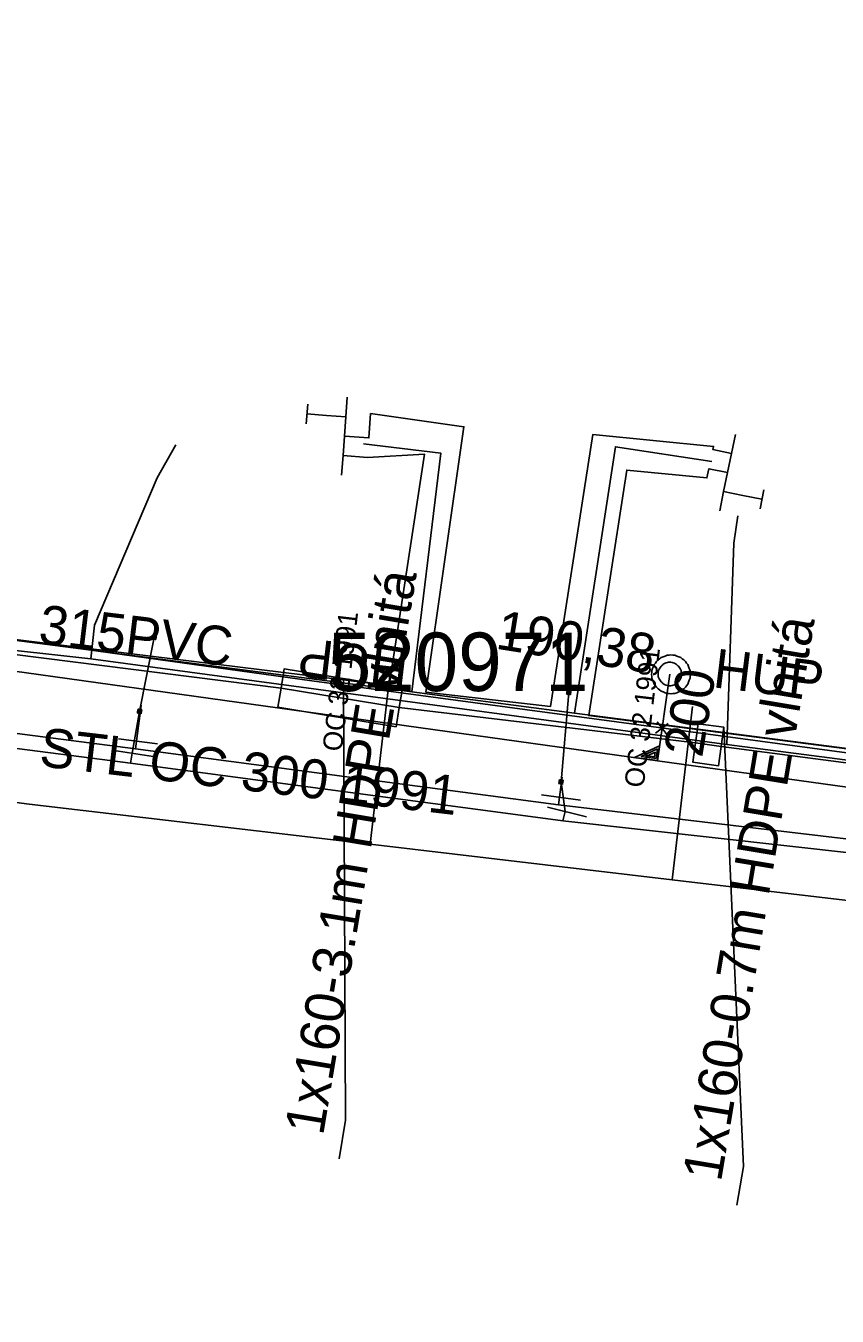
# Model space of a CAD drawing. Extents: x -746464 to -745690, y -1051581 to -1049993.
# Drawn here: x -745918.54 to -745897.73, y -1050642.11 to -1050609 of the extents above; entities that cross this region are included whole.
import ezdxf

# ---------------------------------------------------------------- set-up
doc = ezdxf.new("R2010")
doc.units = 0
for name, color, linetype in [('04_CETIN_sdelovaci_podzem', 7, 'Continuous'), ('45_Eltodo_popisy', 7, 'Continuous'), ('45_Eltodo_vedeni_NN_zemni', 7, 'Continuous'), ('48_Prazs_plynarenska_STL', 7, 'Continuous'), ('48_Prazs_plynarenska_STL_popisy', 7, 'Continuous'), ('51_PVaK_kanal_jednotna_neoverena poloha_pripojka', 7, 'Continuous'), ('51_PVaK_kanal_jednotna_overena poloha_rad', 7, 'Continuous'), ('51_PVaK_kanal_objekty', 7, 'Continuous'), ('51_PVaK_kanal_popisy', 7, 'Continuous'), ('51_PVaK_vodovod_chranicky_objekty', 7, 'Continuous'), ('51_PVaK_vodovod_neoverena poloha_pripojka', 7, 'Continuous'), ('51_PVaK_vodovod_overena poloha_pripojka', 7, 'Continuous'), ('51_PVaK_vodovod_overena poloha_rad', 7, 'Continuous'), ('51_PVaK_vodovod_zruseno_neoverena poloha', 7, 'Continuous'), ('55_PREdi_chranicky', 7, 'Continuous'), ('55_PREdi_NN', 7, 'Continuous'), ('55_PREdi_NN_pripojovaci_misto', 7, 'Continuous'), ('55_PREdi_stavby_popisy', 7, 'Continuous'), ('55_PREdi_VN', 7, 'Continuous')]:
    doc.layers.add(name, color=color, linetype=linetype)

msp = doc.modelspace()

# ---------------------------------------------------------------- linework, layer by layer
at = {"layer": '04_CETIN_sdelovaci_podzem'}
for points in [[(-745863.25, -1050609), (-745863.73, -1050611.95), (-745870.36, -1050631.21), (-745887.77, -1050629.2), (-745891.41, -1050628.63), (-745900.56, -1050627.44)], [(-745916.87, -1050625.24), (-745916.78, -1050624.38), (-745915.17, -1050620.6), (-745914.69, -1050619.75)], [(-745900.27, -1050621.57), (-745900.38, -1050622.27), (-745900.56, -1050627.44)], [(-745916.87, -1050625.24), (-745922.59, -1050624.61), (-745926.58, -1050624.12), (-745928.53, -1050623.83), (-745932.3, -1050623.37), (-745939.73, -1050622.43)], [(-745900.56, -1050627.44), (-745916.87, -1050625.24)]]:
    msp.add_lwpolyline(points, dxfattribs=at)
at = {"layer": '45_Eltodo_vedeni_NN_zemni'}
for points in [[(-745932.464, -1050622.851), (-745911.205, -1050625.806)], [(-745911.205, -1050625.806), (-745891.44, -1050628.465)]]:
    msp.add_lwpolyline(points, dxfattribs=at)
at = {"layer": '48_Prazs_plynarenska_STL'}
for points in [[(-745983.23, -1050618.3), (-745982.423, -1050618.479), (-745972.466, -1050620.693), (-745959.98, -1050623.47), (-745928.028, -1050627.702), (-745918.45, -1050628.97), (-745909.707, -1050630), (-745901.96, -1050630.912), (-745885.25, -1050632.88), (-745867.974, -1050634.924), (-745862.77, -1050635.54), (-745858.93, -1050638.49), (-745858.68, -1050642.05), (-745857.88, -1050642.106)], [(-745909.707, -1050630), (-745909.18, -1050625.527)], [(-745901.96, -1050630.912), (-745901.437, -1050626.468)]]:
    msp.add_lwpolyline(points, dxfattribs=at)
at = {"layer": '51_PVaK_kanal_jednotna_neoverena poloha_pripojka'}
msp.add_line((-745902.02, -1050625.63), (-745902.338, -1050627.854), dxfattribs=at)
at = {"layer": '51_PVaK_kanal_jednotna_overena poloha_rad'}
msp.add_lwpolyline([(-745889.28, -1050629.67), (-745902.338, -1050627.854), (-745923.93, -1050624.851), (-745928.486, -1050624.217), (-745945.72, -1050621.82)], dxfattribs=at)
at = {"layer": '51_PVaK_kanal_objekty'}
for p, q in [((-745902.34, -1050626.853), (-745902.086, -1050627.189)), ((-745902.39, -1050627.15), (-745902.058, -1050626.898))]:
    msp.add_line(p, q, dxfattribs=at)
for points in [[(-745901.49, -1050625.64), (-745901.5, -1050625.59), (-745901.5, -1050625.54), (-745901.52, -1050625.49), (-745901.54, -1050625.44), (-745901.56, -1050625.39), (-745901.59, -1050625.35), (-745901.62, -1050625.31), (-745901.66, -1050625.27), (-745901.7, -1050625.24), (-745901.74, -1050625.21), (-745901.79, -1050625.19), (-745901.84, -1050625.17), (-745901.89, -1050625.15), (-745901.94, -1050625.15), (-745901.99, -1050625.14), (-745902.04, -1050625.15), (-745902.09, -1050625.15), (-745902.14, -1050625.17), (-745902.19, -1050625.19), (-745902.24, -1050625.21), (-745902.28, -1050625.24), (-745902.32, -1050625.27), (-745902.36, -1050625.31), (-745902.39, -1050625.35), (-745902.42, -1050625.39), (-745902.44, -1050625.44), (-745902.46, -1050625.49), (-745902.48, -1050625.54), (-745902.48, -1050625.59), (-745902.49, -1050625.64), (-745902.48, -1050625.69), (-745902.48, -1050625.74), (-745902.46, -1050625.79), (-745902.44, -1050625.84), (-745902.42, -1050625.89), (-745902.39, -1050625.93), (-745902.36, -1050625.97), (-745902.32, -1050626.01), (-745902.28, -1050626.04), (-745902.24, -1050626.07), (-745902.19, -1050626.09), (-745902.14, -1050626.11), (-745902.09, -1050626.13), (-745902.04, -1050626.13), (-745901.99, -1050626.14), (-745901.94, -1050626.13), (-745901.89, -1050626.13), (-745901.84, -1050626.11), (-745901.79, -1050626.09), (-745901.74, -1050626.07), (-745901.7, -1050626.04), (-745901.66, -1050626.01), (-745901.62, -1050625.97), (-745901.59, -1050625.93), (-745901.56, -1050625.89), (-745901.54, -1050625.84), (-745901.52, -1050625.79), (-745901.5, -1050625.74), (-745901.5, -1050625.69), (-745901.49, -1050625.64)], [(-745901.72, -1050625.63), (-745901.72, -1050625.6), (-745901.726, -1050625.57), (-745901.732, -1050625.54), (-745901.744, -1050625.51), (-745901.762, -1050625.48), (-745901.78, -1050625.456), (-745901.798, -1050625.432), (-745901.822, -1050625.408), (-745901.846, -1050625.39), (-745901.87, -1050625.372), (-745901.9, -1050625.354), (-745901.93, -1050625.342), (-745901.96, -1050625.336), (-745901.99, -1050625.33), (-745902.02, -1050625.33), (-745902.05, -1050625.33), (-745902.08, -1050625.336), (-745902.11, -1050625.342), (-745902.14, -1050625.354), (-745902.17, -1050625.372), (-745902.194, -1050625.39), (-745902.218, -1050625.408), (-745902.242, -1050625.432), (-745902.26, -1050625.456), (-745902.278, -1050625.48), (-745902.296, -1050625.51), (-745902.308, -1050625.54), (-745902.314, -1050625.57), (-745902.32, -1050625.6), (-745902.32, -1050625.63), (-745902.32, -1050625.66), (-745902.314, -1050625.69), (-745902.308, -1050625.72), (-745902.296, -1050625.75), (-745902.278, -1050625.78), (-745902.26, -1050625.804), (-745902.242, -1050625.828), (-745902.218, -1050625.852), (-745902.194, -1050625.87), (-745902.17, -1050625.888), (-745902.14, -1050625.906), (-745902.11, -1050625.918), (-745902.08, -1050625.924), (-745902.05, -1050625.93), (-745902.02, -1050625.93), (-745901.99, -1050625.93), (-745901.96, -1050625.924), (-745901.93, -1050625.918), (-745901.9, -1050625.906), (-745901.87, -1050625.888), (-745901.846, -1050625.87), (-745901.822, -1050625.852), (-745901.798, -1050625.828), (-745901.78, -1050625.804), (-745901.762, -1050625.78), (-745901.744, -1050625.75), (-745901.732, -1050625.72), (-745901.726, -1050625.69), (-745901.72, -1050625.66), (-745901.72, -1050625.63)], [(-745902.217, -1050627.018), (-745902.333, -1050627.853), (-745902.929, -1050627.77), (-745902.281, -1050627.476)], [(-745902.336, -1050627.554), (-745902.37, -1050627.797), (-745902.75, -1050627.744), (-745902.332, -1050627.554)], [(-745902.392, -1050627.635), (-745902.409, -1050627.757), (-745902.604, -1050627.73), (-745902.388, -1050627.636)]]:
    msp.add_lwpolyline(points, dxfattribs=at)
at = {"layer": '51_PVaK_vodovod_chranicky_objekty'}
for p, q in [((-745915.303, -1050624.733), (-745915.192, -1050624.646)), ((-745915.303, -1050624.733), (-745915.301, -1050624.713)), ((-745915.303, -1050624.733), (-745915.284, -1050624.735)), ((-745915.291, -1050624.633), (-745915.293, -1050624.653)), ((-745915.204, -1050624.745), (-745915.291, -1050624.633)), ((-745915.291, -1050624.633), (-745915.271, -1050624.636)), ((-745915.204, -1050624.745), (-745915.224, -1050624.743)), ((-745915.192, -1050624.646), (-745915.211, -1050624.644)), ((-745915.204, -1050624.745), (-745915.202, -1050624.725)), ((-745915.192, -1050624.646), (-745915.194, -1050624.666)), ((-745904.668, -1050626.148), (-745904.555, -1050626.062)), ((-745904.668, -1050626.148), (-745904.665, -1050626.128)), ((-745904.668, -1050626.148), (-745904.648, -1050626.15)), ((-745904.654, -1050626.048), (-745904.657, -1050626.068)), ((-745904.569, -1050626.161), (-745904.654, -1050626.048)), ((-745904.654, -1050626.048), (-745904.634, -1050626.051)), ((-745904.569, -1050626.161), (-745904.588, -1050626.159)), ((-745904.555, -1050626.062), (-745904.575, -1050626.059)), ((-745904.569, -1050626.161), (-745904.566, -1050626.141)), ((-745904.555, -1050626.062), (-745904.558, -1050626.082)), ((-745915.679, -1050626.628), (-745915.562, -1050626.549)), ((-745915.679, -1050626.628), (-745915.676, -1050626.609)), ((-745915.679, -1050626.628), (-745915.66, -1050626.632)), ((-745915.66, -1050626.53), (-745915.664, -1050626.55)), ((-745915.581, -1050626.648), (-745915.66, -1050626.53)), ((-745915.66, -1050626.53), (-745915.641, -1050626.534)), ((-745915.581, -1050626.648), (-745915.601, -1050626.644)), ((-745915.562, -1050626.549), (-745915.582, -1050626.546)), ((-745915.581, -1050626.648), (-745915.578, -1050626.628)), ((-745915.562, -1050626.549), (-745915.566, -1050626.569)), ((-745915.16, -1050627.418), (-745916.16, -1050627.292)), ((-745915.27, -1050627.743), (-745916.27, -1050627.589)), ((-745904.867, -1050628.441), (-745904.754, -1050628.357)), ((-745904.867, -1050628.441), (-745904.865, -1050628.421)), ((-745904.867, -1050628.441), (-745904.848, -1050628.444)), ((-745904.853, -1050628.342), (-745904.856, -1050628.362)), ((-745904.769, -1050628.456), (-745904.853, -1050628.342)), ((-745904.853, -1050628.342), (-745904.833, -1050628.345)), ((-745904.769, -1050628.456), (-745904.788, -1050628.453)), ((-745904.754, -1050628.357), (-745904.774, -1050628.354)), ((-745904.769, -1050628.456), (-745904.766, -1050628.436)), ((-745904.754, -1050628.357), (-745904.757, -1050628.376)), ((-745904.31, -1050628.863), (-745905.31, -1050628.727)), ((-745904.16, -1050629.295), (-745905.16, -1050629.045))]:
    msp.add_line(p, q, dxfattribs=at)
for points in [[(-745915.241, -1050624.64), (-745915.246, -1050624.639), (-745915.251, -1050624.64), (-745915.256, -1050624.64), (-745915.261, -1050624.641), (-745915.267, -1050624.644), (-745915.271, -1050624.646), (-745915.275, -1050624.648), (-745915.28, -1050624.652), (-745915.283, -1050624.656), (-745915.287, -1050624.659), (-745915.291, -1050624.664), (-745915.293, -1050624.668), (-745915.295, -1050624.673), (-745915.296, -1050624.678), (-745915.297, -1050624.683), (-745915.298, -1050624.688), (-745915.297, -1050624.693), (-745915.297, -1050624.698), (-745915.296, -1050624.703), (-745915.293, -1050624.709), (-745915.291, -1050624.713), (-745915.288, -1050624.717), (-745915.285, -1050624.722), (-745915.281, -1050624.725), (-745915.278, -1050624.729), (-745915.273, -1050624.732), (-745915.268, -1050624.735), (-745915.264, -1050624.737), (-745915.259, -1050624.738), (-745915.254, -1050624.739), (-745915.249, -1050624.74), (-745915.244, -1050624.739), (-745915.239, -1050624.739), (-745915.233, -1050624.738), (-745915.228, -1050624.735), (-745915.224, -1050624.733), (-745915.219, -1050624.73), (-745915.215, -1050624.727), (-745915.211, -1050624.723), (-745915.208, -1050624.72), (-745915.204, -1050624.715), (-745915.202, -1050624.71), (-745915.2, -1050624.706), (-745915.199, -1050624.701), (-745915.198, -1050624.696), (-745915.197, -1050624.691), (-745915.198, -1050624.686), (-745915.198, -1050624.681), (-745915.199, -1050624.675), (-745915.202, -1050624.67), (-745915.204, -1050624.666), (-745915.207, -1050624.661), (-745915.21, -1050624.657), (-745915.214, -1050624.653), (-745915.217, -1050624.65), (-745915.222, -1050624.646), (-745915.226, -1050624.644), (-745915.231, -1050624.642), (-745915.236, -1050624.64), (-745915.241, -1050624.64)], [(-745904.604, -1050626.055), (-745904.609, -1050626.055), (-745904.614, -1050626.055), (-745904.62, -1050626.055), (-745904.625, -1050626.057), (-745904.63, -1050626.059), (-745904.634, -1050626.061), (-745904.639, -1050626.064), (-745904.643, -1050626.067), (-745904.647, -1050626.071), (-745904.65, -1050626.074), (-745904.654, -1050626.079), (-745904.657, -1050626.083), (-745904.658, -1050626.088), (-745904.66, -1050626.093), (-745904.661, -1050626.098), (-745904.661, -1050626.103), (-745904.661, -1050626.108), (-745904.661, -1050626.113), (-745904.66, -1050626.118), (-745904.657, -1050626.124), (-745904.655, -1050626.128), (-745904.652, -1050626.132), (-745904.649, -1050626.137), (-745904.645, -1050626.141), (-745904.642, -1050626.144), (-745904.637, -1050626.148), (-745904.633, -1050626.15), (-745904.628, -1050626.152), (-745904.623, -1050626.154), (-745904.618, -1050626.154), (-745904.613, -1050626.155), (-745904.608, -1050626.155), (-745904.603, -1050626.154), (-745904.598, -1050626.153), (-745904.592, -1050626.151), (-745904.588, -1050626.148), (-745904.584, -1050626.146), (-745904.579, -1050626.143), (-745904.576, -1050626.139), (-745904.572, -1050626.136), (-745904.568, -1050626.131), (-745904.566, -1050626.126), (-745904.564, -1050626.122), (-745904.562, -1050626.117), (-745904.562, -1050626.112), (-745904.561, -1050626.107), (-745904.561, -1050626.102), (-745904.562, -1050626.097), (-745904.563, -1050626.091), (-745904.565, -1050626.086), (-745904.568, -1050626.082), (-745904.57, -1050626.077), (-745904.573, -1050626.073), (-745904.577, -1050626.069), (-745904.581, -1050626.066), (-745904.585, -1050626.062), (-745904.59, -1050626.059), (-745904.595, -1050626.058), (-745904.599, -1050626.056), (-745904.604, -1050626.055)], [(-745915.611, -1050626.54), (-745915.616, -1050626.539), (-745915.621, -1050626.539), (-745915.626, -1050626.539), (-745915.632, -1050626.54), (-745915.637, -1050626.542), (-745915.642, -1050626.544), (-745915.646, -1050626.546), (-745915.651, -1050626.549), (-745915.654, -1050626.553), (-745915.658, -1050626.556), (-745915.662, -1050626.56), (-745915.665, -1050626.565), (-745915.667, -1050626.57), (-745915.669, -1050626.574), (-745915.67, -1050626.579), (-745915.671, -1050626.584), (-745915.671, -1050626.589), (-745915.671, -1050626.594), (-745915.67, -1050626.6), (-745915.668, -1050626.605), (-745915.666, -1050626.61), (-745915.663, -1050626.614), (-745915.66, -1050626.619), (-745915.657, -1050626.622), (-745915.654, -1050626.626), (-745915.649, -1050626.63), (-745915.645, -1050626.633), (-745915.64, -1050626.635), (-745915.635, -1050626.637), (-745915.63, -1050626.638), (-745915.626, -1050626.639), (-745915.62, -1050626.639), (-745915.615, -1050626.639), (-745915.61, -1050626.638), (-745915.605, -1050626.636), (-745915.6, -1050626.634), (-745915.596, -1050626.631), (-745915.591, -1050626.628), (-745915.587, -1050626.625), (-745915.583, -1050626.622), (-745915.58, -1050626.617), (-745915.577, -1050626.613), (-745915.575, -1050626.608), (-745915.573, -1050626.603), (-745915.572, -1050626.598), (-745915.571, -1050626.594), (-745915.571, -1050626.588), (-745915.571, -1050626.583), (-745915.572, -1050626.578), (-745915.574, -1050626.573), (-745915.576, -1050626.568), (-745915.578, -1050626.564), (-745915.581, -1050626.559), (-745915.585, -1050626.555), (-745915.588, -1050626.551), (-745915.592, -1050626.548), (-745915.597, -1050626.545), (-745915.602, -1050626.543), (-745915.606, -1050626.541), (-745915.611, -1050626.54)], [(-745904.804, -1050628.349), (-745904.809, -1050628.349), (-745904.814, -1050628.349), (-745904.819, -1050628.349), (-745904.824, -1050628.35), (-745904.829, -1050628.353), (-745904.834, -1050628.355), (-745904.838, -1050628.358), (-745904.843, -1050628.361), (-745904.846, -1050628.364), (-745904.85, -1050628.368), (-745904.854, -1050628.372), (-745904.856, -1050628.377), (-745904.858, -1050628.382), (-745904.86, -1050628.387), (-745904.86, -1050628.392), (-745904.861, -1050628.397), (-745904.861, -1050628.402), (-745904.86, -1050628.407), (-745904.859, -1050628.412), (-745904.857, -1050628.417), (-745904.855, -1050628.422), (-745904.852, -1050628.426), (-745904.849, -1050628.431), (-745904.845, -1050628.434), (-745904.842, -1050628.438), (-745904.837, -1050628.442), (-745904.833, -1050628.444), (-745904.828, -1050628.446), (-745904.823, -1050628.448), (-745904.818, -1050628.448), (-745904.813, -1050628.449), (-745904.808, -1050628.449), (-745904.803, -1050628.449), (-745904.798, -1050628.447), (-745904.792, -1050628.445), (-745904.788, -1050628.443), (-745904.783, -1050628.44), (-745904.779, -1050628.437), (-745904.775, -1050628.433), (-745904.772, -1050628.43), (-745904.768, -1050628.425), (-745904.765, -1050628.421), (-745904.764, -1050628.416), (-745904.762, -1050628.411), (-745904.761, -1050628.406), (-745904.761, -1050628.401), (-745904.761, -1050628.396), (-745904.761, -1050628.391), (-745904.762, -1050628.386), (-745904.765, -1050628.38), (-745904.767, -1050628.376), (-745904.77, -1050628.372), (-745904.773, -1050628.367), (-745904.776, -1050628.363), (-745904.78, -1050628.36), (-745904.784, -1050628.356), (-745904.789, -1050628.354), (-745904.794, -1050628.352), (-745904.799, -1050628.35), (-745904.804, -1050628.349)]]:
    msp.add_lwpolyline(points, dxfattribs=at)
at = {"layer": '51_PVaK_vodovod_neoverena poloha_pripojka'}
for p, q in [((-745915.62, -1050626.59), (-745915.247, -1050624.69)), ((-745904.81, -1050628.4), (-745904.61, -1050626.106))]:
    msp.add_line(p, q, dxfattribs=at)
at = {"layer": '51_PVaK_vodovod_overena poloha_pripojka'}
for p, q in [((-745915.81, -1050627.66), (-745915.62, -1050626.59)), ((-745915.85, -1050627.92), (-745915.81, -1050627.66)), ((-745904.7, -1050629.16), (-745904.81, -1050628.4)), ((-745904.76, -1050629.4), (-745904.7, -1050629.16))]:
    msp.add_line(p, q, dxfattribs=at)
at = {"layer": '51_PVaK_vodovod_overena poloha_rad'}
msp.add_lwpolyline([(-746014.36, -1050609.69), (-745980.95, -1050617.57), (-745973.36, -1050619.03), (-745961.92, -1050621.25), (-745930.63, -1050626.01), (-745915.85, -1050627.92), (-745904.76, -1050629.4), (-745861.02, -1050634.28), (-745853.46, -1050635.14)], dxfattribs=at)
at = {"layer": '51_PVaK_vodovod_zruseno_neoverena poloha'}
for p, q in [((-745915.7, -1050627.35), (-745915.584, -1050626.441)), ((-745915.725, -1050627.548), (-745915.7, -1050627.35)), ((-745904.85, -1050628.79), (-745904.779, -1050628.278)), ((-745904.877, -1050628.988), (-745904.85, -1050628.79))]:
    msp.add_line(p, q, dxfattribs=at)
msp.add_lwpolyline([(-745852.68, -1050634.63), (-745861.154, -1050634.158), (-745904.877, -1050628.988), (-745915.725, -1050627.548), (-745930.855, -1050625.588), (-745955.81, -1050621.59), (-745962.129, -1050620.616), (-745973.33, -1050618.19), (-745981.008, -1050616.706), (-746015.55, -1050609.24)], dxfattribs=at)
at = {"layer": '55_PREdi_chranicky'}
for points in [[(-745908.96, -1050626.49), (-745909.041, -1050626.983), (-745912.071, -1050626.483), (-745911.99, -1050625.99), (-745911.909, -1050625.497), (-745908.879, -1050625.997), (-745908.96, -1050626.49)], [(-745900.7, -1050627.49), (-745900.768, -1050627.985), (-745901.428, -1050627.895), (-745901.36, -1050627.4), (-745901.292, -1050626.905), (-745900.632, -1050626.995), (-745900.7, -1050627.49)]]:
    msp.add_lwpolyline(points, close=True, dxfattribs=at)
at = {"layer": '55_PREdi_NN'}
for points in [[(-745941.276, -1050615.374), (-745941.761, -1050615.308), (-745941.78, -1050615.444), (-745943.23, -1050615.309), (-745944.039, -1050621.644), (-745909.222, -1050625.923), (-745908.312, -1050619.993), (-745909.776, -1050620.072), (-745910.401, -1050620.027)], [(-745910.437, -1050620.526), (-745910.401, -1050620.027), (-745910.365, -1050619.529), (-745910.329, -1050619.03), (-745910.293, -1050618.531)], [(-745910.329, -1050619.03), (-745910.828, -1050618.994)], [(-745910.365, -1050619.529), (-745909.74, -1050619.574), (-745909.694, -1050618.948), (-745907.301, -1050619.285), (-745908.278, -1050626.092), (-745905.076, -1050626.463), (-745903.998, -1050619.487), (-745900.897, -1050619.791), (-745900.914, -1050619.872), (-745900.434, -1050619.972)], [(-745900.332, -1050619.483), (-745900.434, -1050619.972), (-745900.536, -1050620.462), (-745900.638, -1050620.951), (-745900.74, -1050621.441)], [(-745909.879, -1050619.727), (-745907.893, -1050619.968), (-745908.637, -1050626.091)], [(-745900.943, -1050620.176), (-745903.415, -1050619.798), (-745904.462, -1050626.634)], [(-745900.536, -1050620.462), (-745901.016, -1050620.362), (-745901.066, -1050620.599), (-745903.122, -1050620.397), (-745904.099, -1050626.698), (-745868.887, -1050631.245), (-745868.748, -1050630.164)], [(-745900.638, -1050620.951), (-745900.148, -1050621.053)], [(-745944.434, -1050621.562), (-745930.73, -1050623.253), (-745926.485, -1050623.772), (-745908.637, -1050626.091)], [(-745908.637, -1050626.091), (-745904.462, -1050626.634)], [(-745904.462, -1050626.634), (-745885.467, -1050629.102), (-745868.633, -1050631.278), (-745867.096, -1050635.424), (-745859.716, -1050636.248), (-745850.771, -1050639.444), (-745849.486, -1050639.903), (-745843.016, -1050640.727), (-745840.316, -1050641.071)]]:
    msp.add_lwpolyline(points, dxfattribs=at)
at = {"layer": '55_PREdi_NN_pripojovaci_misto'}
for p, q in [((-745911.309, -1050618.71), (-745911.344, -1050619.209)), ((-745910.828, -1050618.994), (-745911.327, -1050618.959)), ((-745900.148, -1050621.053), (-745899.657, -1050621.148)), ((-745899.705, -1050621.394), (-745899.609, -1050620.903))]:
    msp.add_line(p, q, dxfattribs=at)
at = {"layer": '55_PREdi_stavby_popisy'}
for points in [[(-745910.504, -1050638.067), (-745910.34, -1050637.081), (-745910.394, -1050625.747)], [(-745900.297, -1050639.256), (-745900.132, -1050638.269), (-745900.632, -1050626.995)]]:
    msp.add_lwpolyline(points, dxfattribs=at)
at = {"layer": '55_PREdi_VN'}
msp.add_lwpolyline([(-745880.52, -1050629.74), (-745887.65, -1050629.04), (-745891.22, -1050628.73), (-745900.7, -1050627.49), (-745901.36, -1050627.4), (-745908.96, -1050626.49), (-745911.99, -1050625.99), (-745921.94, -1050624.74), (-745926.66, -1050624.04), (-745928.94, -1050623.66), (-745931.98, -1050623.2), (-745941.45, -1050622.2), (-745944.29, -1050621.51), (-745948.24, -1050620.95), (-745953.42, -1050620.14), (-745956.65, -1050619.37), (-745961.25, -1050618.45), (-745968.47, -1050616.85), (-745975.42, -1050615.47), (-745985.66, -1050613.08)], dxfattribs=at)
msp.add_lwpolyline([(-745880.52, -1050629.74), (-745887.65, -1050629.04), (-745891.22, -1050628.73), (-745900.7, -1050627.49), (-745901.36, -1050627.4), (-745908.96, -1050626.49), (-745911.99, -1050625.99), (-745921.94, -1050624.74), (-745926.66, -1050624.04), (-745928.94, -1050623.66), (-745931.98, -1050623.2), (-745941.45, -1050622.2), (-745944.29, -1050621.51), (-745948.24, -1050620.95), (-745953.42, -1050620.14), (-745956.65, -1050619.37), (-745961.25, -1050618.45), (-745968.47, -1050616.85), (-745975.42, -1050615.47), (-745985.66, -1050613.08)], dxfattribs=at)

# ---------------------------------------------------------------- texts
at = {"layer": '45_Eltodo_popisy'}
msp.add_text('520971', height=1.5, dxfattribs=at).set_placement((-745910.795, -1050626.068))
at = {"layer": '48_Prazs_plynarenska_STL_popisy'}
for s, height, rotation, p in [('OC 32 1991', 0.5, 83.2805, (-745910.435, -1050627.635)), ('HUP', 1, 173.28, (-745908.68, -1050625.027)), ('OC 32 1991', 0.5, 83.2879, (-745902.69, -1050628.562)), ('HUP', 1, 353, (-745900.937, -1050625.968)), ('STL OC 300 1991', 1, 353.281, (-745918.22, -1050627.99))]:
    msp.add_text(s, height=height, rotation=rotation, dxfattribs=at).set_placement(p)
at = {"layer": '51_PVaK_kanal_popisy'}
for s, rotation, p in [('315PVC', 353.0817, (-745918.241, -1050624.84)), ('190,38', 350.9015, (-745906.515, -1050624.975)), ('200', 80.8629, (-745901.191, -1050627.796))]:
    msp.add_text(s, height=1, rotation=rotation, dxfattribs=at).set_placement(p)
at = {"layer": '55_PREdi_stavby_popisy'}
for s, p in [('1x160-3.1m HDPE vlnitá', (-745910.915, -1050637.492)), ('1x160-0.7m HDPE vlnitá', (-745900.707, -1050638.681))]:
    msp.add_text(s, height=1, rotation=80.5424, dxfattribs=at).set_placement(p)

doc.saveas('drawing.dxf')
